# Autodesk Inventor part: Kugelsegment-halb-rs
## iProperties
Created: 2006-08
Part Number: Kugelsegment-halb-rs
Document SubType Name: Modeling
Designer: TB13 - rsc
Manufacturer: Standard
Standards Organization: Custom
Author: TB13 - rsc
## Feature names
1. Basis1
2. Trennen1
3. Trennen2
4. Spiegeln1 [Mirror]
